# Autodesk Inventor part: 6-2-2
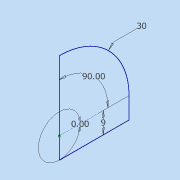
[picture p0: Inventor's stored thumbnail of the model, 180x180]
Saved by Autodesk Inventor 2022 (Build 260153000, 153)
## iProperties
Created: 2021-07
Part Number: 6-2-2
Material: 一般
Document SubType Name: Modeling
Designer: DesignLab
Density: 1 g/cm^3
Appearance: 既定
Author: DesignLab
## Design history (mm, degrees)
sketch "スケッチ1"
  geometry: L1 (0, 0)-(30, 0); L2 (0, 0)-(30, 0); L3 (0, 0)-(0, 30); L4 (30, 0)-(30, -9); L5 (30, -9)-(0, -9); L6 (0, -9)-(0, 30); A1 r 30 centre (0, 0) between (30, 0) and (0, 30); 1 further point
  constraints: 12 end point, 2 point on circle, 2 vertical, 1 centre point, 1 coincident, 1 collinear, 1 horizontal, 1 perpendicular
  dimensions: "d0" = 30 radius of A1; "d1" = 0 distance between parallel lines of L1 L2; "d2" = 90 deg angle of L1 L3; "d3" = 9 distance of L2.end L4.end
